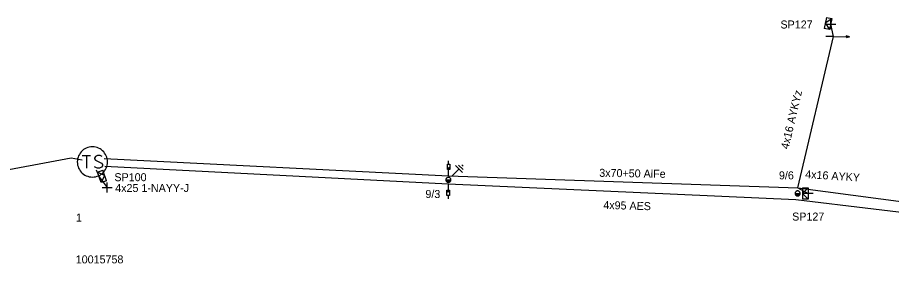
# Model space of a CAD drawing. Extents: x -717562 to -713845, y -1151196 to -1143903.
# Drawn here: x -714276.3 to -714167.1, y -1147034.5 to -1147003.7 of the extents above; entities that cross this region are included whole.
import ezdxf

# ---------------------------------------------------------------- set-up
doc = ezdxf.new("R2010")
doc.units = 0
for name, color, linetype in [('Vrstva 1', 7, 'Continuous'), ('Vrstva 12', 7, 'Continuous'), ('Vrstva 13', 7, 'Continuous'), ('Vrstva 14', 7, 'Continuous'), ('Vrstva 15', 7, 'Continuous'), ('Vrstva 16', 7, 'Continuous'), ('Vrstva 2', 7, 'Continuous'), ('Vrstva 25', 7, 'Continuous'), ('Vrstva 26', 7, 'Continuous'), ('Vrstva 27', 7, 'Continuous'), ('Vrstva 31', 7, 'Continuous'), ('Vrstva 33', 7, 'Continuous'), ('Vrstva 34', 7, 'Continuous'), ('Vrstva 5', 7, 'Continuous'), ('Vrstva 50', 7, 'Continuous'), ('Vrstva 51', 7, 'Continuous'), ('Vrstva 52', 7, 'Continuous'), ('Vrstva 54', 7, 'Continuous'), ('Vrstva 55', 7, 'Continuous'), ('Vrstva 59', 7, 'Continuous'), ('Vrstva 6', 7, 'Continuous'), ('Vrstva 9', 7, 'Continuous')]:
    doc.layers.add(name, color=color, linetype=linetype)

# ---------------------------------------------------------------- blocks, each defined once
blk = doc.blocks.new('NN440')
at = {"layer": 'Vrstva 2'}
for points in [[(0.63, 0), (0.63, 0.06), (0.62, 0.13), (0.6, 0.19), (0.58, 0.25), (0.55, 0.31), (0.51, 0.37), (0.47, 0.42), (0.42, 0.46), (0.37, 0.51), (0.32, 0.54), (0.26, 0.57), (0.2, 0.59), (0.13, 0.61), (0.07, 0.62), (0, 0.63), (-0.06, 0.62), (-0.13, 0.61), (-0.19, 0.59), (-0.26, 0.57), (-0.31, 0.54), (-0.37, 0.51), (-0.42, 0.46), (-0.47, 0.42), (-0.51, 0.37), (-0.54, 0.31), (-0.57, 0.25), (-0.6, 0.19), (-0.62, 0.13), (-0.63, 0.06), (-0.63, 0), (-0.63, -0.07), (-0.62, -0.14), (-0.6, -0.2), (-0.57, -0.26), (-0.54, -0.32), (-0.51, -0.37), (-0.47, -0.43), (-0.42, -0.47), (-0.37, -0.51), (-0.31, -0.55), (-0.26, -0.58), (-0.19, -0.6), (-0.13, -0.62), (-0.06, -0.63), (0, -0.63), (0.07, -0.63), (0.13, -0.62), (0.2, -0.6), (0.26, -0.58), (0.32, -0.55), (0.37, -0.51), (0.42, -0.47), (0.47, -0.43), (0.51, -0.37), (0.55, -0.32), (0.58, -0.26), (0.6, -0.2), (0.62, -0.14), (0.63, -0.07), (0.63, 0)], [(-0.63, 0), (0.63, 0)], [(-0.6, -0.18), (0.57, -0.18)], [(-0.51, -0.32), (0.5, -0.32)], [(-0.37, -0.47), (0.35, -0.47)]]:
    blk.add_lwpolyline(points, dxfattribs=at)
blk = doc.blocks.new('NN560')
at = {"layer": 'Vrstva 2'}
for points in [[(2, 0), (1.59, 0.14)], [(0, 0), (2, 0)], [(2, 0), (1.59, -0.13)]]:
    blk.add_lwpolyline(points, dxfattribs=at)
blk = doc.blocks.new('NN800')
at = {"layer": 'Vrstva 1'}
for points in [[(-0.44, 0.44), (0.44, -0.44)], [(-0.44, -0.44), (0.44, 0.44)]]:
    blk.add_lwpolyline(points, dxfattribs=at)
blk = doc.blocks.new('NN820')
at = {"layer": 'Vrstva 13'}
for points in [[(0, 0), (0, -1.05)], [(-0.16, -0.81), (0.16, -0.81)], [(-0.16, -1.47), (-0.16, -0.81)], [(0, -1.05), (-0.06, -0.93)], [(0, -1.05), (0.06, -0.93)], [(0.16, -0.81), (0.16, -1.47)], [(0.16, -1.47), (-0.16, -1.47)], [(0, -1.47), (0, -1.87)]]:
    blk.add_lwpolyline(points, dxfattribs=at)
blk = doc.blocks.new('NN630')
at = {"layer": 'Vrstva 9'}
for points in [[(0, -0.7), (-0.7, 0)], [(-0.7, -0.7), (-0.7, 0), (0.7, 0), (0.7, -0.7)], [(-0.7, -0.7), (0.7, -0.7)], [(0, -0.7), (0.7, 0)]]:
    blk.add_lwpolyline(points, dxfattribs=at)
blk = doc.blocks.new('NN810')
at = {"layer": 'Vrstva 14'}
for points in [[(0, -0.64), (0, -1.89)], [(0.63, -1.89), (-0.62, -1.89)], [(0.39, -2.2), (-0.4, -2.2)], [(0, -2.52), (-0.12, -2.52)], [(0.14, -2.52), (0, -2.52)]]:
    blk.add_lwpolyline(points, dxfattribs=at)
blk = doc.blocks.new('NN610')
at = {"layer": 'Vrstva 6'}
for points in [[(1.88, 0), (1.87, 0.2), (1.84, 0.39), (1.79, 0.58), (1.72, 0.77), (1.63, 0.94), (1.52, 1.11), (1.4, 1.26), (1.26, 1.4), (1.1, 1.53), (0.94, 1.63), (0.76, 1.72), (0.58, 1.8), (0.19, 1.88), (0.19, 1.88), (-0.01, 1.89), (-0.21, 1.88), (-0.4, 1.85), (-0.59, 1.8), (-0.78, 1.72), (-0.95, 1.63), (-1.12, 1.53), (-1.27, 1.4), (-1.41, 1.26), (-1.54, 1.11), (-1.64, 0.94), (-1.73, 0.77), (-1.8, 0.58), (-1.86, 0.39), (-1.89, 0.2), (-1.9, 0), (-1.89, -0.2), (-1.86, -0.39), (-1.8, -0.58), (-1.73, -0.77), (-1.64, -0.95), (-1.54, -1.11), (-1.41, -1.27), (-1.27, -1.41), (-1.12, -1.53), (-0.95, -1.64), (-0.78, -1.73), (-0.59, -1.8), (-0.4, -1.85), (-0.21, -1.88), (-0.01, -1.89), (0.19, -1.88), (0.39, -1.85), (0.58, -1.8), (0.76, -1.73), (0.94, -1.64), (1.1, -1.53), (1.26, -1.41), (1.4, -1.27), (1.52, -1.11), (1.63, -0.95), (1.72, -0.77), (1.79, -0.58), (1.84, -0.39), (1.87, -0.2), (1.88, 0)], [(-1.27, 0.78), (-0.26, 0.78)], [(-0.76, 0.78), (-0.76, -0.79)], [(1.19, 0.66), (0.94, 0.78), (0.62, 0.78), (0.37, 0.66), (0.24, 0.47), (0.24, 0.4), (0.37, 0.22), (1.12, -0.16), (1.25, -0.32), (1.25, -0.48), (1.12, -0.67), (0.87, -0.79), (0.62, -0.79), (0.49, -0.73), (0.24, -0.6)]]:
    blk.add_lwpolyline(points, dxfattribs=at)
blk = doc.blocks.new('NN510')
at = {"layer": 'Vrstva 2'}
blk.add_lwpolyline([(0, 0), (0, 0.94)], dxfattribs=at)

msp = doc.modelspace()

# ---------------------------------------------------------------- linework, layer by layer
at = {"layer": 'Vrstva 1'}
msp.add_lwpolyline([(-714265.43, -1147021.34), (-714222.41, -1147023.52), (-714178.81, -1147025.04), (-714140.15, -1147030.14), (-714118.86, -1147032.12)], dxfattribs=at)
at = {"layer": 'Vrstva 5'}
for points in [[(-714268.2, -1147021.56), (-714269.57, -1147021.32), (-714291.17, -1147025.34)], [(-714266.44, -1147022.79), (-714266.06, -1147023.66)]]:
    msp.add_lwpolyline(points, dxfattribs=at)
at = {"layer": 'Vrstva 50'}
msp.add_lwpolyline([(-714265.35, -1147022.3), (-714222.47, -1147024.52), (-714179.05, -1147026.46), (-714140.24, -1147031.13), (-714120, -1147033.08), (-714118.9, -1147032.69)], dxfattribs=at)
at = {"layer": 'Vrstva 52'}
msp.add_lwpolyline([(-714178.81, -1147025.04), (-714177.5, -1147025.74)], dxfattribs=at)
at = {"layer": 'Vrstva 54'}
msp.add_lwpolyline([(-714178.81, -1147025.04), (-714174.35, -1147006.1), (-714174.68, -1147004.56)], dxfattribs=at)
at = {"layer": 'Vrstva 59'}
msp.add_lwpolyline([(-714266.06, -1147023.66), (-714265.07, -1147024.96)], dxfattribs=at)

# ---------------------------------------------------------------- block references
at = {"layer": 'Vrstva 13'}
for name, rotation in [('NN510', 90), ('NN560', -1.9992861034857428)]:
    msp.add_blockref(name, (-714174.35, -1147006.1), dxfattribs=dict(at, rotation=rotation))
at = {"layer": 'Vrstva 13', "xscale": 0.5, "yscale": 0.5}
msp.add_blockref('NN440', (-714222.44, -1147024.02), dxfattribs=at)
at = {"layer": 'Vrstva 13', "xscale": 0.49999999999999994, "yscale": 0.5, "rotation": -3.6200112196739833}
msp.add_blockref('NN440', (-714178.82, -1147025.72), dxfattribs=at)
at = {"layer": 'Vrstva 15', "rotation": 135.43425561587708}
msp.add_blockref('NN810', (-714222.44, -1147024.02), dxfattribs=at)
at = {"layer": 'Vrstva 16', "rotation": 180}
msp.add_blockref('NN820', (-714222.41, -1147023.52), dxfattribs=at)
at = {"layer": 'Vrstva 16'}
msp.add_blockref('NN820', (-714222.47, -1147024.52), dxfattribs=at)
at = {"layer": 'Vrstva 25'}
msp.add_blockref('NN610', (-714266.89, -1147021.78), dxfattribs=at)
at = {"layer": 'Vrstva 31'}
for p, rotation in [((-714174.68, -1147004.56), -101.25537497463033), ((-714266.04, -1147023.71), 108.53255657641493), ((-714177.5, -1147025.74), -90)]:
    msp.add_blockref('NN630', p, dxfattribs=dict(at, rotation=rotation))
at = {"layer": 'Vrstva 34'}
for p, rotation in [((-714174.68, -1147004.56), 45), ((-714265.07, -1147024.96), 45), ((-714177.5, -1147025.74), -135.47067779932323)]:
    msp.add_blockref('NN800', p, dxfattribs=dict(at, rotation=rotation))

# ---------------------------------------------------------------- texts
at = {"layer": 'Vrstva 12'}
for s, p in [('9/6', (-714181.15, -1147023.96)), ('9/3', (-714225.31, -1147026.29))]:
    msp.add_text(s, height=1, dxfattribs=at).set_placement(p)
at = {"layer": 'Vrstva 2'}
msp.add_text('3x70+50 AlFe', height=1, rotation=359.079, dxfattribs=at).set_placement((-714203.6, -1147023.64))
at = {"layer": 'Vrstva 26'}
msp.add_text('10015758', height=1, dxfattribs=at).set_placement((-714268.98, -1147034.46))
at = {"layer": 'Vrstva 27'}
msp.add_text('1', height=1, dxfattribs=at).set_placement((-714268.95, -1147029.24))
at = {"layer": 'Vrstva 33'}
for s, p in [('SP127', (-714180.96, -1147005.11)), ('SP100', (-714264.15, -1147024.19)), ('SP127', (-714179.5, -1147029.11))]:
    msp.add_text(s, height=1, dxfattribs=at).set_placement(p)
at = {"layer": 'Vrstva 51'}
msp.add_text('4x95 AES', height=1, rotation=358.512, dxfattribs=at).set_placement((-714203.1, -1147027.66))
at = {"layer": 'Vrstva 54'}
msp.add_text('4x16 AYKY', height=1, rotation=356.334, dxfattribs=at).set_placement((-714177.89, -1147023.8))
at = {"layer": 'Vrstva 55'}
msp.add_text('4x16 AYKYz', height=1, rotation=76.749, dxfattribs=at).set_placement((-714179.96, -1147020.25))
at = {"layer": 'Vrstva 6'}
msp.add_text('4x25 1-NAYY-J', height=1, dxfattribs=at).set_placement((-714264.05, -1147025.54))

doc.saveas('drawing.dxf')
